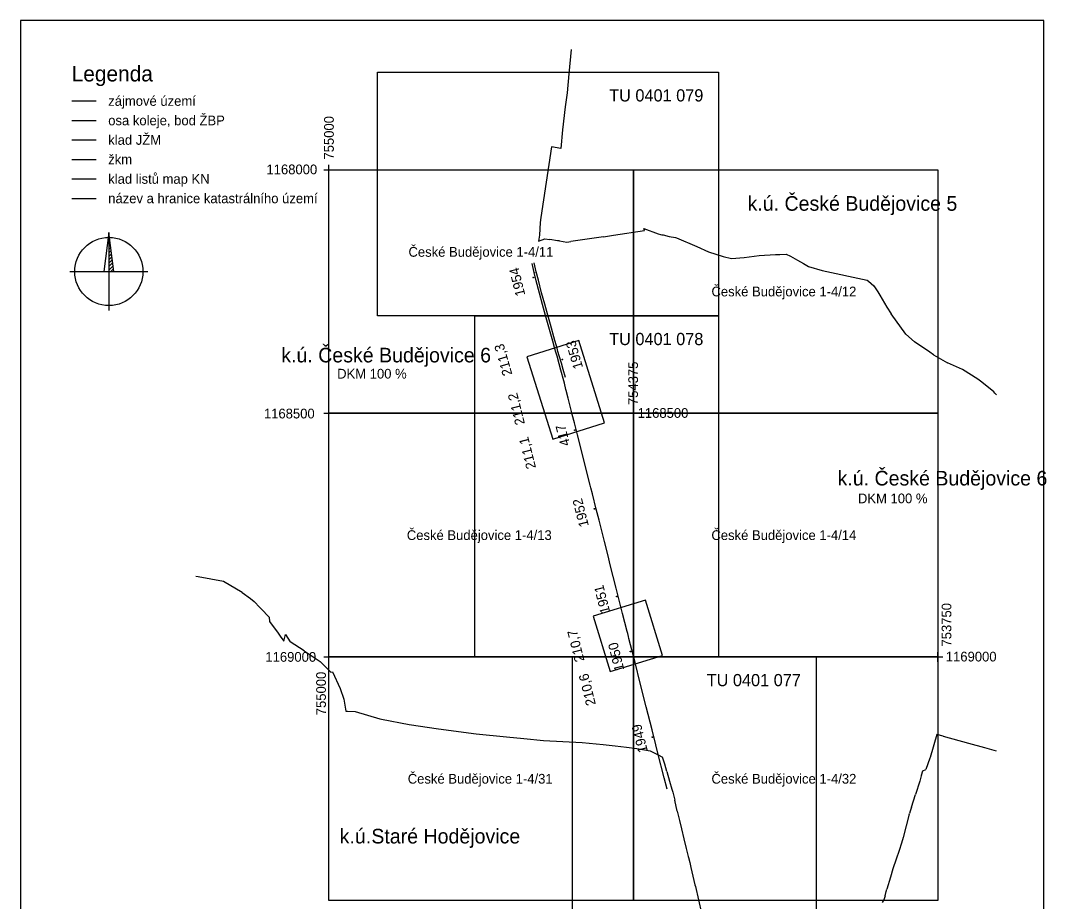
# Model space of a CAD drawing. Extents: x -755632 to -753527, y -1170664 to -1167694.
# Drawn here: x -755632 to -753527, y -1169502 to -1167694 of the extents above; entities that cross this region are included whole.
import ezdxf

# ---------------------------------------------------------------- set-up
doc = ezdxf.new("R2010")
doc.units = 0
for name, color, linetype in [('Vrstva 1', 7, 'Continuous'), ('Vrstva 13', 7, 'Continuous'), ('Vrstva 23', 7, 'Continuous'), ('Vrstva 24', 7, 'Continuous'), ('Vrstva 3', 7, 'Continuous'), ('Vrstva 61', 7, 'Continuous'), ('Vrstva 62', 7, 'Continuous'), ('Vrstva 63', 7, 'Continuous'), ('Vrstva 7', 7, 'Continuous')]:
    doc.layers.add(name, color=color, linetype=linetype)

# ---------------------------------------------------------------- blocks, each defined once
blk = doc.blocks.new('C083_1')
at = {"layer": 'Vrstva 1'}
blk.add_circle((0, 0), 0.4, dxfattribs=at)
blk = doc.blocks.new('C015')
at = {"layer": 'Vrstva 63'}
blk.add_line((0, 0), (0.1, 0), dxfattribs=at)
blk.add_circle((0, 0), 0.756, dxfattribs=at)

msp = doc.modelspace()

# ---------------------------------------------------------------- linework, layer by layer
at = {"layer": 'Vrstva 1'}
for p, q in [((-755527.5, -1167898.9), (-755477.5, -1167898.9)), ((-755527.5, -1167938.9), (-755477.5, -1167938.9)), ((-754578.4, -1168211.1), (-754582.8, -1168192.4)), ((-754574.2, -1168209.7), (-754578.4, -1168191.4)), ((-754574.3, -1168227.9), (-754578.4, -1168211.1)), ((-754567.7, -1168253.5), (-754574.3, -1168227.9)), ((-754569.9, -1168227), (-754574.2, -1168209.7)), ((-754563.3, -1168252.5), (-754569.9, -1168227)), ((-754561.5, -1168276.9), (-754567.7, -1168253.5)), ((-754556.9, -1168275.7), (-754563.3, -1168252.5)), ((-754555.3, -1168299.5), (-754561.5, -1168276.9)), ((-754550.6, -1168298.4), (-754556.9, -1168275.7)), ((-754549.8, -1168318.7), (-754555.3, -1168299.5)), ((-754545.3, -1168317.4), (-754550.6, -1168298.4)), ((-754540.3, -1168352.2), (-754549.8, -1168318.7)), ((-754536, -1168350.8), (-754545.3, -1168317.4)), ((-754535.9, -1168367.7), (-754540.3, -1168352.2)), ((-754471.7, -1168615.4), (-754483.6, -1168568.3)), ((-754463.6, -1168647.3), (-754471.7, -1168615.4)), ((-754462.3, -1168652.6), (-754463.6, -1168647.3)), ((-754459.1, -1168665.2), (-754462.3, -1168652.6)), ((-754451.1, -1168696.9), (-754459.1, -1168665.2)), ((-754445.4, -1168719.2), (-754451.1, -1168696.9)), ((-754439.1, -1168744.1), (-754445.4, -1168719.2)), ((-754434.2, -1168763.4), (-754439.1, -1168744.1)), ((-754426.9, -1168792.7), (-754434.2, -1168763.4)), ((-754422.3, -1168810.8), (-754426.9, -1168792.7)), ((-754410.2, -1168858.7), (-754422.3, -1168810.8)), ((-754348.6, -1169102.3), (-754360.9, -1169053.8)), ((-754336.7, -1169149.4), (-754348.6, -1169102.3)), ((-754328.9, -1169180.2), (-754336.7, -1169149.4)), ((-754324.5, -1169197.4), (-754328.9, -1169180.2)), ((-754311.8, -1169247.9), (-754324.5, -1169197.4)), ((-754305.8, -1169271.6), (-754311.8, -1169247.9))]:
    msp.add_line(p, q, dxfattribs=at)
for points in [[(-754900, -1168300), (-754900, -1167800), (-754200, -1167800), (-754200, -1168300), (-754900, -1168300)], [(-754700, -1169000), (-754700, -1168300), (-754200, -1168300), (-754200, -1169000), (-754700, -1169000)], [(-754483.6, -1168568.3), (-754489.7, -1168544.1), (-754495.9, -1168519.7), (-754500.2, -1168502.6), (-754500.2, -1168502.5), (-754500.4, -1168501.8), (-754506.6, -1168477.2), (-754508.7, -1168468.8), (-754512.6, -1168453.5), (-754513.2, -1168451), (-754516.5, -1168438.4), (-754517.8, -1168433.2), (-754523.6, -1168411.5), (-754527.2, -1168398.3), (-754531.5, -1168383), (-754534, -1168374.3), (-754535.9, -1168367.7), (-754540.3, -1168352.2)], [(-754514, -1168426.2), (-754518.8, -1168410), (-754522.7, -1168397.1), (-754527.2, -1168381.9), (-754529.7, -1168373.2), (-754531.6, -1168366.5), (-754536, -1168350.8)], [(-754360.9, -1169053.8), (-754371.5, -1169011.7), (-754383.9, -1168962.4), (-754385, -1168958.3), (-754386.6, -1168952.1), (-754387.6, -1168947.8), (-754397, -1168910.6), (-754410.2, -1168858.7)], [(-754500, -1169700), (-754500, -1169000), (-754000, -1169000), (-754000, -1169700), (-754500, -1169700)]]:
    msp.add_lwpolyline(points, dxfattribs=at)
at = {"layer": 'Vrstva 13'}
for p, q in [((-754502.3, -1167753.4), (-754507.3, -1167803.1)), ((-754507.3, -1167803.1), (-754511, -1167842.3)), ((-754511, -1167842.3), (-754515, -1167870.9)), ((-754515, -1167870.9), (-754520.1, -1167918.4)), ((-754520.1, -1167918.4), (-754524.1, -1167956.3)), ((-754543.2, -1167953.4), (-754564.9, -1168098.4)), ((-754524.1, -1167956.3), (-754543.2, -1167953.4)), ((-755527.5, -1168058.9), (-755477.5, -1168058.9)), ((-754564.9, -1168098.4), (-754566.2, -1168108.1)), ((-754566.2, -1168108.1), (-754567.3, -1168134.2)), ((-754352, -1168125.1), (-754353.3, -1168121)), ((-754353.3, -1168121), (-754324.1, -1168131.6)), ((-754567.3, -1168134.2), (-754569.8, -1168146.6)), ((-754569.8, -1168146.6), (-754556.6, -1168142)), ((-754556.6, -1168142), (-754546.1, -1168143.5)), ((-754530.6, -1168145.7), (-754546.1, -1168143.5)), ((-754436.1, -1168137.5), (-754503, -1168147.5)), ((-754436.1, -1168137.5), (-754415.9, -1168134.5)), ((-754415.9, -1168134.5), (-754352, -1168125.1)), ((-754324.1, -1168131.6), (-754319.1, -1168132.7)), ((-754319.1, -1168132.7), (-754316.2, -1168133.4)), ((-754316.2, -1168133.4), (-754313.7, -1168134)), ((-754313.7, -1168134), (-754301.2, -1168136.8)), ((-754301.2, -1168136.8), (-754288.6, -1168139.3)), ((-754288.6, -1168139.3), (-754286.3, -1168139.8)), ((-754286.3, -1168139.8), (-754244.4, -1168157.8)), ((-754526.6, -1168146.2), (-754530.6, -1168145.7)), ((-754526.6, -1168146.2), (-754511.2, -1168148.7)), ((-754511.2, -1168148.7), (-754503, -1168147.5)), ((-754244.4, -1168157.8), (-754220.8, -1168168.8)), ((-754220.8, -1168168.8), (-754191, -1168178.2)), ((-754191, -1168178.2), (-754173.8, -1168182.2)), ((-754173.8, -1168182.2), (-754147.5, -1168180.4)), ((-754147.5, -1168180.4), (-754117, -1168175.9)), ((-754117, -1168175.9), (-754083.1, -1168174.1)), ((-754083.1, -1168174.1), (-754074.6, -1168173.8)), ((-754074.6, -1168173.8), (-754061.5, -1168173.3)), ((-754061.5, -1168173.3), (-754052.6, -1168177.6)), ((-754052.6, -1168177.6), (-754038.2, -1168185.9)), ((-754038.2, -1168185.9), (-754025.7, -1168192.8)), ((-754025.7, -1168192.8), (-754015.7, -1168198.6)), ((-754015.7, -1168198.6), (-753987.4, -1168206.9)), ((-753987.4, -1168206.9), (-753895.3, -1168226.4)), ((-753895.3, -1168226.4), (-753892.7, -1168228.7)), ((-753892.7, -1168228.7), (-753881.2, -1168238.2)), ((-753881.2, -1168238.2), (-753873.3, -1168250.8)), ((-753873.3, -1168250.8), (-753869.5, -1168257.4)), ((-753869.5, -1168257.4), (-753854.5, -1168282)), ((-753854.5, -1168282), (-753846, -1168295.6)), ((-753815.8, -1168337.3), (-753846, -1168295.6)), ((-753798.3, -1168353.2), (-753815.8, -1168337.3)), ((-753766.6, -1168374.8), (-753798.3, -1168353.2)), ((-753758.9, -1168380.1), (-753766.6, -1168374.8)), ((-753758.9, -1168380.1), (-753730.2, -1168396.6)), ((-753699.5, -1168410.1), (-753730.2, -1168396.6)), ((-753668.4, -1168429.6), (-753699.5, -1168410.1)), ((-753660.1, -1168436.4), (-753668.4, -1168429.6)), ((-753635.3, -1168456.2), (-753660.1, -1168436.4)), ((-753633.1, -1168458.7), (-753635.3, -1168456.2)), ((-753629.6, -1168462.4), (-753633.1, -1168458.7)), ((-755267.9, -1168835.3), (-755272.6, -1168834.6)), ((-755216.2, -1168845.4), (-755267.9, -1168835.3)), ((-755177.7, -1168867.9), (-755216.2, -1168845.4)), ((-755177.7, -1168867.9), (-755160.8, -1168879.9)), ((-755160.8, -1168879.9), (-755153.1, -1168886)), ((-755153.1, -1168886), (-755141.6, -1168898.4)), ((-755141.6, -1168898.4), (-755135.3, -1168904.9)), ((-755135.3, -1168904.9), (-755125.7, -1168915)), ((-755125.7, -1168915), (-755122.5, -1168918.2)), ((-755122.5, -1168918.2), (-755121.4, -1168927.2)), ((-755121.4, -1168927.2), (-755104, -1168951.5)), ((-755104, -1168951.5), (-755099.7, -1168957.2)), ((-755099.7, -1168957.2), (-755092, -1168967.6)), ((-755092, -1168967.6), (-755088.5, -1168954.2)), ((-755088.5, -1168954.2), (-755079.3, -1168968.9)), ((-755050.3, -1168987.6), (-755079.3, -1168968.9)), ((-755050.3, -1168987.6), (-755042.5, -1168992.8)), ((-755042.5, -1168992.8), (-755017.7, -1169009.3)), ((-754995.6, -1169031.3), (-755017.7, -1169009.3)), ((-754995.6, -1169031.3), (-754992, -1169030.4)), ((-754992, -1169030.4), (-754976.8, -1169064.7)), ((-754976.8, -1169064.7), (-754969.2, -1169086.5)), ((-754969.2, -1169086.5), (-754964.7, -1169111.6)), ((-754964.7, -1169111.6), (-754961.3, -1169111.2)), ((-754961.3, -1169111.2), (-754946.1, -1169112.2)), ((-754946.1, -1169112.2), (-754895.4, -1169126.7)), ((-754895.4, -1169126.7), (-754892, -1169127.5)), ((-754892, -1169127.5), (-754835.3, -1169138.4)), ((-754835.3, -1169138.4), (-754774.9, -1169147.5)), ((-754774.9, -1169147.5), (-754697.7, -1169157.6)), ((-754697.7, -1169157.6), (-754635.3, -1169163.9)), ((-754635.3, -1169163.9), (-754599.4, -1169167.4)), ((-754599.4, -1169167.4), (-754559.5, -1169171.2)), ((-754559.5, -1169171.2), (-754480.1, -1169175.8)), ((-753752.5, -1169159.2), (-753766.2, -1169206.4)), ((-753739.1, -1169162.9), (-753752.5, -1169159.2)), ((-753738.4, -1169163.1), (-753739.1, -1169162.9)), ((-753686.6, -1169177.7), (-753738.4, -1169163.1)), ((-754480.1, -1169175.8), (-754436.7, -1169179.6)), ((-754436.7, -1169179.6), (-754412.6, -1169182.6)), ((-754412.6, -1169182.6), (-754389, -1169184.9)), ((-754389, -1169184.9), (-754368.1, -1169188.2)), ((-754368.1, -1169188.2), (-754340.5, -1169192.9)), ((-754340.5, -1169192.9), (-754337.7, -1169194)), ((-754337.7, -1169194), (-754332.3, -1169196.7)), ((-753686.3, -1169177.7), (-753686.6, -1169177.7)), ((-753653.8, -1169186.8), (-753686.3, -1169177.7)), ((-753629.6, -1169193.6), (-753653.8, -1169186.8)), ((-754332.3, -1169196.7), (-754324.1, -1169200.8)), ((-754324.1, -1169200.8), (-754314.9, -1169205.4)), ((-754310.6, -1169220.3), (-754314.9, -1169205.4)), ((-753766.8, -1169207.8), (-753770.6, -1169219.2)), ((-753766.2, -1169206.4), (-753766.8, -1169207.8)), ((-754306.3, -1169235.1), (-754310.6, -1169220.3)), ((-754306.3, -1169235.1), (-754300.7, -1169254.8)), ((-753783.9, -1169242.6), (-753781.2, -1169233.5)), ((-753781.2, -1169233.5), (-753774.9, -1169230.7)), ((-753770.6, -1169219.2), (-753774.9, -1169230.7)), ((-754300.7, -1169254.8), (-754295.8, -1169271.6)), ((-753787.2, -1169254.6), (-753796, -1169282.1)), ((-753784.3, -1169243.9), (-753787.2, -1169254.6)), ((-753783.9, -1169242.6), (-753784.3, -1169243.9)), ((-754295.8, -1169271.6), (-754294.7, -1169275.6)), ((-754294.7, -1169275.6), (-754294.2, -1169277.2)), ((-754294.2, -1169277.2), (-754290.1, -1169294.2)), ((-754284.9, -1169316.2), (-754290.1, -1169294.2)), ((-753804, -1169308.4), (-753796, -1169282.1)), ((-754284.9, -1169316.2), (-754280.1, -1169335.9)), ((-753808.9, -1169322.4), (-753821.3, -1169370.3)), ((-753808.9, -1169322.4), (-753808.5, -1169321.2)), ((-753806.9, -1169316.8), (-753808.5, -1169321.2)), ((-753804, -1169308.4), (-753806.9, -1169316.8)), ((-754280.1, -1169335.9), (-754276.1, -1169352.8)), ((-754276.1, -1169352.8), (-754271.2, -1169373.1)), ((-754271.2, -1169373.1), (-754266.5, -1169392.9)), ((-753824.7, -1169382), (-753829.7, -1169396.9)), ((-753821.3, -1169370.3), (-753824.7, -1169382)), ((-754266.5, -1169392.9), (-754266.4, -1169393.2)), ((-754266.4, -1169393.2), (-754262.3, -1169409.8)), ((-753829.7, -1169396.9), (-753836, -1169415.1)), ((-754262.3, -1169409.8), (-754261.9, -1169411.4)), ((-754261.9, -1169411.4), (-754259.4, -1169422.1)), ((-754259.4, -1169422.1), (-754257.1, -1169431.8)), ((-753836, -1169415.1), (-753842.7, -1169434.9)), ((-754257.1, -1169431.8), (-754248.5, -1169467.4)), ((-753842.7, -1169434.9), (-753847.6, -1169451.8)), ((-754248.5, -1169467.4), (-754247.6, -1169471.2)), ((-753847.6, -1169451.8), (-753854.7, -1169476.5)), ((-754247.6, -1169471.2), (-754235, -1169525.8)), ((-753858.5, -1169490), (-753861, -1169498.6)), ((-753858.5, -1169490), (-753856.1, -1169481.6)), ((-753856.1, -1169481.6), (-753854.7, -1169476.5)), ((-753861, -1169498.6), (-753864.7, -1169503.7))]:
    msp.add_line(p, q, dxfattribs=at)
at = {"layer": 'Vrstva 23'}
msp.add_line((-755527.5, -1167858.9), (-755477.5, -1167858.9), dxfattribs=at)
for points in [[(-754593.3, -1168383.9), (-754540.2, -1168552.9), (-754433.9, -1168519.5), (-754487.1, -1168350.5)], [(-754349.7, -1168883.6), (-754457.2, -1168916.5), (-754422.5, -1169029.9), (-754315, -1168997)]]:
    msp.add_lwpolyline(points, close=True, dxfattribs=at)
at = {"layer": 'Vrstva 3'}
msp.add_line((-755527.5, -1168018.9), (-755477.5, -1168018.9), dxfattribs=at)
for points in [[(-755000, -1168010), (-755000, -1168000), (-755000, -1167990)], [(-755010, -1168000), (-755000, -1168000), (-754990, -1168000)], [(-755010, -1168500), (-755000, -1168500), (-754990, -1168500)], [(-755000, -1168510), (-755000, -1168500), (-755000, -1168490)], [(-754385, -1168500), (-754375, -1168500), (-754365, -1168500)], [(-754375, -1168510), (-754375, -1168500), (-754375, -1168490)], [(-755010, -1169000), (-755000, -1169000), (-754990, -1169000)], [(-755000, -1169010), (-755000, -1169000), (-755000, -1168990)], [(-753760, -1169000), (-753750, -1169000), (-753740, -1169000)], [(-753750, -1169010), (-753750, -1169000), (-753750, -1168990)]]:
    msp.add_lwpolyline(points, dxfattribs=at)
for points in [[(-754375, -1168000), (-754375, -1168500), (-755000, -1168500), (-755000, -1168000)], [(-753750, -1168000), (-753750, -1168500), (-754375, -1168500), (-754375, -1168000)], [(-754375, -1168500), (-754375, -1169000), (-755000, -1169000), (-755000, -1168500)], [(-753750, -1168500), (-753750, -1169000), (-754375, -1169000), (-754375, -1168500)], [(-754375, -1169000), (-754375, -1169500), (-755000, -1169500), (-755000, -1169000)], [(-753750, -1169000), (-753750, -1169500), (-754375, -1169500), (-754375, -1169000)]]:
    msp.add_lwpolyline(points, close=True, dxfattribs=at)
at = {"layer": 'Vrstva 61'}
msp.add_line((-753532.5, -1167693.9), (-755632.5, -1167693.9), dxfattribs=at)
msp.add_lwpolyline([(-755632.5, -1167693.9), (-755632.5, -1170663.9), (-753532.5, -1170663.9), (-753532.5, -1167693.9)], dxfattribs=at)
at = {"layer": 'Vrstva 62'}
for p, q in [((-755451.2, -1168129), (-755451.2, -1168289)), ((-755451.2, -1168135.4), (-755450.5, -1168134.7)), ((-755451.2, -1168142.4), (-755449.7, -1168141)), ((-755451.2, -1168149.5), (-755448.9, -1168147.2)), ((-755451.2, -1168156.6), (-755448.1, -1168153.5)), ((-755451.2, -1168163.7), (-755447.3, -1168159.8)), ((-755451.2, -1168170.7), (-755446.6, -1168166.1)), ((-755451.2, -1168177.8), (-755445.8, -1168172.4)), ((-755451.2, -1168184.9), (-755445, -1168178.7)), ((-755451.2, -1168191.9), (-755444.2, -1168185)), ((-755451.2, -1168199), (-755443.4, -1168191.2)), ((-755451.2, -1168206.1), (-755442.6, -1168197.5)), ((-755447.1, -1168209), (-755441.8, -1168203.8)), ((-755531.2, -1168209), (-755371.2, -1168209))]:
    msp.add_line(p, q, dxfattribs=at)
for points in [[(-755451.2, -1168129), (-755461.2, -1168209)], [(-755451.2, -1168129), (-755451.2, -1168209), (-755441.2, -1168209), (-755451.2, -1168129)]]:
    msp.add_lwpolyline(points, dxfattribs=at)
msp.add_circle((-755451.2, -1168209), 70, dxfattribs=at)
at = {"layer": 'Vrstva 63'}
for p, q in [((-754520.6, -1168389.7), (-754520.6, -1168389.6)), ((-754495.3, -1168534.7), (-754495.3, -1168534.8)), ((-754409.1, -1168876), (-754409.2, -1168875.9)), ((-754380.9, -1168989.1), (-754381, -1168989))]:
    msp.add_line(p, q, dxfattribs=at)
for centre in [(-754520.6, -1168389.7), (-754495.3, -1168534.7), (-754409.1, -1168875.9), (-754380.9, -1168989)]:
    msp.add_circle(centre, 0.756, dxfattribs=at)
at = {"layer": 'Vrstva 7'}
msp.add_line((-755527.5, -1167978.9), (-755477.5, -1167978.9), dxfattribs=at)

# ---------------------------------------------------------------- block references
at = {"layer": 'Vrstva 1', "rotation": -76.1395985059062}
msp.add_blockref('C083_1', (-754578.4, -1168211.1), dxfattribs=at)
at = {"layer": 'Vrstva 63'}
for p, rotation in [((-754580.3, -1168221.2), -76.1395986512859), ((-754454.7, -1168696), 104.18687417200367), ((-754336, -1169164.8), -75.81077126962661)]:
    msp.add_blockref('C015', p, dxfattribs=dict(at, rotation=rotation))

# ---------------------------------------------------------------- texts
at = {"layer": 'Vrstva 1'}
for s, height, p in [('TU 0401 079', 25, (-754424.6, -1167860)), ('klad JŽM', 20, (-755452.5, -1167948.9)), ('TU 0401 078', 25, (-754424.6, -1168360)), ('TU 0401 077', 25, (-754224.5, -1169060))]:
    msp.add_text(s, height=height, dxfattribs=at).set_placement(p)
at = {"layer": 'Vrstva 13'}
msp.add_text('název a hranice katastrálního území', height=20, dxfattribs=at).set_placement((-755452.5, -1168068.9))
at = {"layer": 'Vrstva 23'}
msp.add_text('zájmové území', height=20, dxfattribs=at).set_placement((-755452.5, -1167868.9))
at = {"layer": 'Vrstva 24'}
for s, height, p in [('k.ú. České Budějovice 5', 30, (-754140.6, -1168084.3)), ('k.ú. České Budějovice 6', 30, (-755097.4, -1168395.5)), ('DKM 100 %', 20, (-754982.8, -1168428.7)), ('k.ú. České Budějovice 6', 30, (-753955.9, -1168648.1)), ('DKM 100 %', 20, (-753914.1, -1168684.6)), ('k.ú. ', 30, (-754977.6, -1169382.8)), ('Staré Hodějovice ', 30, (-754912.6, -1169382.8))]:
    msp.add_text(s, height=height, dxfattribs=at).set_placement(p)
at = {"layer": 'Vrstva 3'}
for s, p in [('755000', (-754989.6, -1167979.2)), ('754375', (-754365.4, -1168483.1)), ('753750', (-753722.4, -1168978.6)), ('755000', (-755005.8, -1169119.6))]:
    msp.add_text(s, height=20, rotation=90, dxfattribs=at).set_placement(p)
for s, p in [('1168000', (-755127.8, -1168009.4)), ('klad listů map KN', (-755452.5, -1168028.9)), ('České Budějovice 1-4/11', (-754836.4, -1168178.7)), ('České Budějovice 1-4/12', (-754214.7, -1168260)), ('1168500', (-755133, -1168510.5)), ('1168500', (-754366.2, -1168509.3)), ('České Budějovice 1-4/13', (-754839.8, -1168760)), ('České Budějovice 1-4/14', (-754214.8, -1168760)), ('1169000', (-755130, -1169009.9)), ('1169000', (-753733.8, -1169009.3)), ('České Budějovice 1-4/31', (-754837.9, -1169260)), ('České Budějovice 1-4/32', (-754214.7, -1169260))]:
    msp.add_text(s, height=20, dxfattribs=at).set_placement(p)
at = {"layer": 'Vrstva 62'}
msp.add_text('Legenda', height=32, dxfattribs=at).set_placement((-755527.5, -1167818.9))
at = {"layer": 'Vrstva 63'}
msp.add_text('osa koleje, bod ŽBP', height=20, dxfattribs=at).set_placement((-755452.5, -1167908.9))
for s, rotation, p in [('1954', 103.8604, (-754596.5, -1168257)), ('1953', 106.4502, (-754477.9, -1168405.8)), ('417', 104.1769, (-754504.6, -1168564.5)), ('1952', 104.1676, (-754466.1, -1168730.6)), ('1951', 104.184, (-754422.2, -1168908.3)), ('1950', 104.1774, (-754393.3, -1169026.1)), ('1949', 104.1892, (-754344.9, -1169193.9))]:
    msp.add_text(s, height=20, rotation=rotation, dxfattribs=at).set_placement(p)
at = {"layer": 'Vrstva 7'}
msp.add_text('žkm', height=20, dxfattribs=at).set_placement((-755452.5, -1167988.9))
for s, rotation, p in [('211,3', 106.0493, (-754623.1, -1168419.9)), ('211,2', 104.1901, (-754597.2, -1168521.3)), ('211,1', 104.1906, (-754574.5, -1168611.6)), ('210,7', 104.1774, (-754475, -1169007.5)), ('210,6', 104.1922, (-754451.7, -1169097.2))]:
    msp.add_text(s, height=20, rotation=rotation, dxfattribs=at).set_placement(p)

doc.saveas('drawing.dxf')
